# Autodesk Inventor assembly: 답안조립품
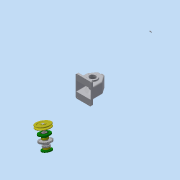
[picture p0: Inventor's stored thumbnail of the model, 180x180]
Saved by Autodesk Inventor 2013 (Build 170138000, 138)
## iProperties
Created: 2016-12
Part Number: 답안조립품
Document SubType Name: Assembly
Designer: narae
Author: narae
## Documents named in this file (14)
- C:\Users\narae\Desktop\461208V1026\답안조립품.iam
- C:\Users\narae\Desktop\461208V1026\V-벨트풀리.ipt
- C:\Users\narae\Desktop\461208V1026\뒤커버.ipt
- C:\Users\narae\Desktop\461208V1026\멈춤나사 - M4x10.ipt
- C:\Users\narae\Desktop\461208V1026\베어링 6203.ipt
- C:\Users\narae\Desktop\461208V1026\본체.ipt
- C:\Users\narae\Desktop\461208V1026\부시.ipt
- C:\Users\narae\Desktop\461208V1026\스퍼기어.ipt
- C:\Users\narae\Desktop\461208V1026\앞커버.ipt
- C:\Users\narae\Desktop\461208V1026\오일씰 28 40 8.ipt
- C:\Users\narae\Desktop\461208V1026\축.ipt
- C:\Users\narae\Desktop\461208V1026\키 - 5 x 5 x 18.ipt
- C:\Users\narae\Desktop\461208V1026\볼트 M3 x 10.ipt
- C:\Users\narae\Desktop\461208V1026\키 - 6 x 6 x 22.ipt
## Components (3 placed, 2 different names)
1. V-벨트풀리:1
2. ISO 4762 M3 x 10:1
3. ISO 4762 M3 x 10:2
